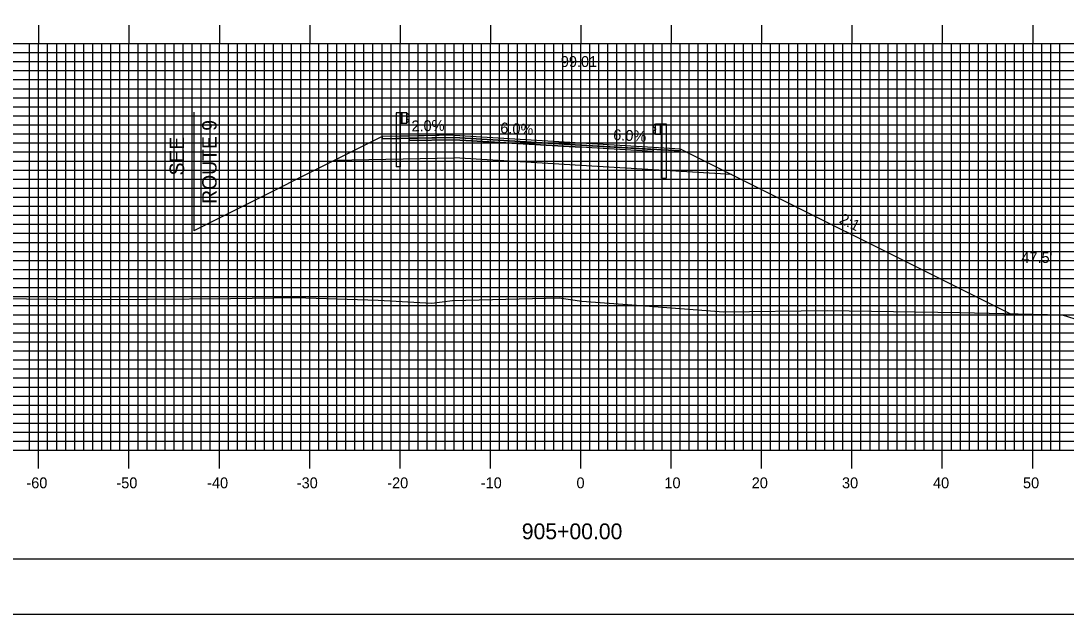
# Model space of a CAD drawing. Extents: x 857504 to 857847, y 364765 to 364985.
# Drawn here: x 857607.4 to 857723, y 364765.2 to 364830.8 of the extents above; entities that cross this region are included whole.
import ezdxf

# ---------------------------------------------------------------- set-up
doc = ezdxf.new("R2010")
doc.units = 0
for name, color, linetype in [('ANNOTATION', 7, 'Continuous'), ('BORDER', 7, 'Continuous'), ('D_Guardrail_Beam_Lt', 7, 'Continuous'), ('D_Guardrail_Beam_Rt', 7, 'Continuous'), ('D_Roadway_Centerline_Text', 7, 'Continuous'), ('D_Roadway_Edge_Shoulder', 7, 'Continuous'), ('D_Roadway_Edge_TW', 7, 'Continuous'), ('D_Roadway_Pavement', 7, 'Continuous'), ('D_Roadway_SlopeLines', 7, 'Continuous'), ('D_Roadway_SubGrade', 7, 'Continuous'), ('D_Text_Standard', 7, 'Continuous'), ('H_V ANNOTATION', 7, 'Continuous'), ('MAJOR', 7, 'Continuous'), ('MINOR', 7, 'Continuous'), ('PLOT BOUNDARY', 7, 'Continuous'), ('S_Roadway_Centerline', 7, 'Continuous')]:
    doc.layers.add(name, color=color, linetype=linetype)

msp = doc.modelspace()

# ---------------------------------------------------------------- linework, layer by layer
at = {"layer": 'BORDER'}
msp.add_lwpolyline([(857519.71, 364771.3), (857839.71, 364771.3), (857839.71, 364981.3), (857519.71, 364981.3)], close=True, dxfattribs=at)
at = {"layer": 'D_Guardrail_Beam_Lt'}
for p, q in [((857648.88, 364820.64), (857648.88, 364814.64)), ((857649.35, 364820.64), (857648.88, 364820.64)), ((857650.04, 364820.64), (857649.35, 364820.64)), ((857649.35, 364820.64), (857649.35, 364819.47)), ((857649.41, 364820.64), (857649.41, 364819.47)), ((857649.52, 364820.64), (857649.52, 364819.47)), ((857650.04, 364819.47), (857650.04, 364820.64)), ((857650.04, 364820.56), (857650.11, 364820.54)), ((857650.04, 364820.09), (857650.04, 364820.02)), ((857650.27, 364820.29), (857650.07, 364820.16)), ((857650.07, 364819.96), (857650.27, 364819.82)), ((857650.13, 364820.54), (857650.27, 364820.44)), ((857650.27, 364819.68), (857650.13, 364819.58)), ((857649.35, 364819.47), (857650.04, 364819.47)), ((857649.37, 364814.64), (857649.37, 364819.47)), ((857650.11, 364819.57), (857650.04, 364819.56)), ((857649.37, 364814.64), (857648.88, 364814.64))]:
    msp.add_line(p, q, dxfattribs=at)
for centre, major_axis, start_param, end_param in [((857650.12, 364820.09), (-0.0789, 0), 5.323254, 6.283185), ((857650.12, 364820.02), (-0.0789, 0), 6.283185, 7.243116), ((857650.1, 364820.5), (0.0417, 0), 0.959931, 1.376053), ((857650.22, 364820.36), (0.0877, 0), 5.323254, 7.243116), ((857650.22, 364819.75), (0.0877, 0), 5.323254, 7.243116), ((857650.1, 364819.61), (0.0417, 0), 4.907132, 5.323254)]:
    msp.add_ellipse(centre, major_axis=major_axis, ratio=0.995501, start_param=start_param, end_param=end_param, dxfattribs=at)
at = {"layer": 'D_Guardrail_Beam_Rt'}
for p, q in [((857677.49, 364819.32), (857677.35, 364819.22)), ((857677.35, 364819.07), (857677.54, 364818.94)), ((857677.54, 364818.74), (857677.35, 364818.6)), ((857677.58, 364819.34), (857677.5, 364819.32)), ((857677.57, 364818.87), (857677.57, 364818.8)), ((857677.58, 364819.42), (857678.27, 364819.42)), ((857677.58, 364818.25), (857677.58, 364819.42)), ((857678.1, 364819.42), (857678.1, 364818.25)), ((857678.2, 364819.42), (857678.2, 364818.25)), ((857678.27, 364819.42), (857678.74, 364819.42)), ((857678.27, 364819.42), (857678.27, 364818.25)), ((857678.74, 364819.42), (857678.74, 364813.42)), ((857677.35, 364818.46), (857677.49, 364818.36)), ((857677.5, 364818.35), (857677.58, 364818.34)), ((857678.27, 364818.25), (857677.58, 364818.25)), ((857678.25, 364813.42), (857678.25, 364818.25)), ((857678.25, 364813.42), (857678.74, 364813.42))]:
    msp.add_line(p, q, dxfattribs=at)
for centre, major_axis, start_param, end_param in [((857677.4, 364819.14), (-0.0877, 0), 5.323254, 7.243116), ((857677.4, 364818.53), (-0.0877, 0), 5.323254, 7.243116), ((857677.51, 364819.28), (-0.0417, 0), 4.907132, 5.323254), ((857677.5, 364818.87), (0.0789, 0), 0, 0.959931), ((857677.5, 364818.8), (0.0789, 0), 5.323254, 6.283185), ((857677.51, 364818.39), (-0.0417, 0), 0.959931, 1.376053)]:
    msp.add_ellipse(centre, major_axis=major_axis, ratio=0.995501, start_param=start_param, end_param=end_param, dxfattribs=at)
at = {"layer": 'D_Roadway_Edge_Shoulder'}
for points in [[(857655.31, 364818.16), (857650.31, 364818.06), (857650.31, 364818.06), (857647.31, 364818), (857647.31, 364817.75), (857650.31, 364817.81), (857655.31, 364817.91)], [(857655.31, 364818.16), (857647.31, 364818), (857647.31, 364817.75), (857655.31, 364817.91)], [(857669.31, 364817.32), (857677.31, 364816.84), (857677.31, 364816.84), (857680.31, 364816.66), (857680.31, 364816.41), (857669.31, 364817.07)]]:
    msp.add_lwpolyline(points, close=True, dxfattribs=at)
at = {"layer": 'D_Roadway_Edge_TW'}
msp.add_lwpolyline([(857655.31, 364818.16), (857669.31, 364817.32), (857669.31, 364817.07), (857655.31, 364817.91)], close=True, dxfattribs=at)
at = {"layer": 'D_Roadway_Pavement'}
for points in [[(857655.31, 364817.91), (857647.31, 364817.75), (857650.31, 364817.81), (857650.31, 364817.56), (857655.31, 364817.66)], [(857655.31, 364817.91), (857650.31, 364817.81), (857650.31, 364817.56), (857655.31, 364817.66)], [(857655.31, 364817.91), (857669.31, 364817.07), (857669.31, 364816.82), (857655.31, 364817.66)]]:
    msp.add_lwpolyline(points, close=True, dxfattribs=at)
for points in [[(857669.31, 364817.07), (857669.31, 364816.82)], [(857669.31, 364817.07), (857669.31, 364816.82)], [(857669.31, 364817.07), (857669.31, 364816.82)], [(857669.31, 364817.07), (857677.31, 364816.59), (857677.31, 364816.34), (857669.31, 364816.82)], [(857669.31, 364817.07), (857669.31, 364816.82)]]:
    msp.add_lwpolyline(points, dxfattribs=at)
at = {"layer": 'D_Roadway_SlopeLines'}
for points in [[(857647.31, 364818), (857626.48, 364807.58)], [(857680.31, 364816.66), (857716.79, 364798.42)]]:
    msp.add_lwpolyline(points, dxfattribs=at)
at = {"layer": 'D_Roadway_SubGrade'}
msp.add_line((857626.48, 364820.72), (857626.48, 364807.58), dxfattribs=at)
for points in [[(857655.31, 364817.66), (857650.31, 364817.56), (857650.31, 364817.81), (857647.31, 364817.75), (857647.31, 364818), (857642.1, 364815.39), (857655.31, 364815.66)], [(857655.31, 364817.66), (857650.31, 364817.56), (857650.31, 364817.81), (857647.31, 364817.75), (857647.31, 364818), (857642.1, 364815.39), (857655.31, 364815.66)], [(857655.31, 364817.66), (857669.31, 364816.82), (857669.31, 364814.82), (857655.31, 364815.66)], [(857669.31, 364816.82), (857669.31, 364817.07), (857680.31, 364816.41), (857680.31, 364816.66), (857685.99, 364813.82), (857669.31, 364814.82)]]:
    msp.add_lwpolyline(points, close=True, dxfattribs=at)
at = {"layer": 'MAJOR'}
for p, q in [((857609.31, 364830.31), (857609.31, 364828.3)), ((857619.31, 364830.31), (857619.31, 364828.3)), ((857629.31, 364830.31), (857629.31, 364828.3)), ((857639.31, 364830.31), (857639.31, 364828.3)), ((857649.31, 364830.31), (857649.31, 364828.3)), ((857659.31, 364830.31), (857659.31, 364828.3)), ((857669.31, 364830.31), (857669.31, 364828.3)), ((857679.31, 364830.31), (857679.31, 364828.3)), ((857689.31, 364830.31), (857689.31, 364828.3)), ((857699.31, 364830.31), (857699.31, 364828.3)), ((857709.31, 364830.31), (857709.31, 364828.3)), ((857719.31, 364830.31), (857719.31, 364828.3)), ((857529.31, 364828.3), (857809.31, 364828.3)), ((857529.31, 364828.3), (857809.31, 364828.3)), ((857609.31, 364783.3), (857609.31, 364828.3)), ((857619.31, 364783.3), (857619.31, 364828.3)), ((857629.31, 364783.3), (857629.31, 364828.3)), ((857639.31, 364783.3), (857639.31, 364828.3)), ((857649.31, 364783.3), (857649.31, 364828.3)), ((857659.31, 364783.3), (857659.31, 364828.3)), ((857669.31, 364783.3), (857669.31, 364828.3)), ((857679.31, 364783.3), (857679.31, 364828.3)), ((857689.31, 364783.3), (857689.31, 364828.3)), ((857699.31, 364783.3), (857699.31, 364828.3)), ((857709.31, 364783.3), (857709.31, 364828.3)), ((857719.31, 364783.3), (857719.31, 364828.3)), ((857529.31, 364823.3), (857809.31, 364823.3)), ((857529.31, 364818.3), (857809.31, 364818.3)), ((857529.31, 364813.3), (857809.31, 364813.3)), ((857529.31, 364808.3), (857809.31, 364808.3)), ((857529.31, 364803.3), (857809.31, 364803.3)), ((857529.31, 364798.3), (857809.31, 364798.3)), ((857529.31, 364793.3), (857809.31, 364793.3)), ((857529.31, 364788.3), (857809.31, 364788.3)), ((857529.31, 364783.3), (857809.31, 364783.3)), ((857529.31, 364783.3), (857809.31, 364783.3)), ((857609.31, 364781.3), (857609.31, 364783.3)), ((857619.31, 364781.3), (857619.31, 364783.3)), ((857629.31, 364781.3), (857629.31, 364783.3)), ((857639.31, 364781.3), (857639.31, 364783.3)), ((857649.31, 364781.3), (857649.31, 364783.3)), ((857659.31, 364781.3), (857659.31, 364783.3)), ((857669.31, 364781.3), (857669.31, 364783.3)), ((857679.31, 364781.3), (857679.31, 364783.3)), ((857689.31, 364781.3), (857689.31, 364783.3)), ((857699.31, 364781.3), (857699.31, 364783.3)), ((857709.31, 364781.3), (857709.31, 364783.3)), ((857719.31, 364781.3), (857719.31, 364783.3))]:
    msp.add_line(p, q, dxfattribs=at)
at = {"layer": 'MINOR'}
for p, q in [((857608.31, 364783.3), (857608.31, 364828.3)), ((857610.31, 364783.3), (857610.31, 364828.3)), ((857611.31, 364783.3), (857611.31, 364828.3)), ((857612.31, 364783.3), (857612.31, 364828.3)), ((857613.31, 364783.3), (857613.31, 364828.3)), ((857614.31, 364783.3), (857614.31, 364828.3)), ((857615.31, 364783.3), (857615.31, 364828.3)), ((857616.31, 364783.3), (857616.31, 364828.3)), ((857617.31, 364783.3), (857617.31, 364828.3)), ((857618.31, 364783.3), (857618.31, 364828.3)), ((857620.31, 364783.3), (857620.31, 364828.3)), ((857621.31, 364783.3), (857621.31, 364828.3)), ((857622.31, 364783.3), (857622.31, 364828.3)), ((857623.31, 364783.3), (857623.31, 364828.3)), ((857624.31, 364783.3), (857624.31, 364828.3)), ((857625.31, 364783.3), (857625.31, 364828.3)), ((857626.31, 364783.3), (857626.31, 364828.3)), ((857627.31, 364783.3), (857627.31, 364828.3)), ((857628.31, 364783.3), (857628.31, 364828.3)), ((857630.31, 364783.3), (857630.31, 364828.3)), ((857631.31, 364783.3), (857631.31, 364828.3)), ((857632.31, 364783.3), (857632.31, 364828.3)), ((857633.31, 364783.3), (857633.31, 364828.3)), ((857634.31, 364783.3), (857634.31, 364828.3)), ((857635.31, 364783.3), (857635.31, 364828.3)), ((857636.31, 364783.3), (857636.31, 364828.3)), ((857637.31, 364783.3), (857637.31, 364828.3)), ((857638.31, 364783.3), (857638.31, 364828.3)), ((857640.31, 364783.3), (857640.31, 364828.3)), ((857641.31, 364783.3), (857641.31, 364828.3)), ((857642.31, 364783.3), (857642.31, 364828.3)), ((857643.31, 364783.3), (857643.31, 364828.3)), ((857644.31, 364783.3), (857644.31, 364828.3)), ((857645.31, 364783.3), (857645.31, 364828.3)), ((857646.31, 364783.3), (857646.31, 364828.3)), ((857647.31, 364783.3), (857647.31, 364828.3)), ((857648.31, 364783.3), (857648.31, 364828.3)), ((857650.31, 364783.3), (857650.31, 364828.3)), ((857651.31, 364783.3), (857651.31, 364828.3)), ((857652.31, 364783.3), (857652.31, 364828.3)), ((857653.31, 364783.3), (857653.31, 364828.3)), ((857654.31, 364783.3), (857654.31, 364828.3)), ((857655.31, 364783.3), (857655.31, 364828.3)), ((857656.31, 364783.3), (857656.31, 364828.3)), ((857657.31, 364783.3), (857657.31, 364828.3)), ((857658.31, 364783.3), (857658.31, 364828.3)), ((857660.31, 364783.3), (857660.31, 364828.3)), ((857661.31, 364783.3), (857661.31, 364828.3)), ((857662.31, 364783.3), (857662.31, 364828.3)), ((857663.31, 364783.3), (857663.31, 364828.3)), ((857664.31, 364783.3), (857664.31, 364828.3)), ((857665.31, 364783.3), (857665.31, 364828.3)), ((857666.31, 364783.3), (857666.31, 364828.3)), ((857667.31, 364783.3), (857667.31, 364828.3)), ((857668.31, 364783.3), (857668.31, 364828.3)), ((857670.31, 364783.3), (857670.31, 364828.3)), ((857671.31, 364783.3), (857671.31, 364828.3)), ((857672.31, 364783.3), (857672.31, 364828.3)), ((857673.31, 364783.3), (857673.31, 364828.3)), ((857674.31, 364783.3), (857674.31, 364828.3)), ((857675.31, 364783.3), (857675.31, 364828.3)), ((857676.31, 364783.3), (857676.31, 364828.3)), ((857677.31, 364783.3), (857677.31, 364828.3)), ((857678.31, 364783.3), (857678.31, 364828.3)), ((857680.31, 364783.3), (857680.31, 364828.3)), ((857681.31, 364783.3), (857681.31, 364828.3)), ((857682.31, 364783.3), (857682.31, 364828.3)), ((857683.31, 364783.3), (857683.31, 364828.3)), ((857684.31, 364783.3), (857684.31, 364828.3)), ((857685.31, 364783.3), (857685.31, 364828.3)), ((857686.31, 364783.3), (857686.31, 364828.3)), ((857687.31, 364783.3), (857687.31, 364828.3)), ((857688.31, 364783.3), (857688.31, 364828.3)), ((857690.31, 364783.3), (857690.31, 364828.3)), ((857691.31, 364783.3), (857691.31, 364828.3)), ((857692.31, 364783.3), (857692.31, 364828.3)), ((857693.31, 364783.3), (857693.31, 364828.3)), ((857694.31, 364783.3), (857694.31, 364828.3)), ((857695.31, 364783.3), (857695.31, 364828.3)), ((857696.31, 364783.3), (857696.31, 364828.3)), ((857697.31, 364783.3), (857697.31, 364828.3)), ((857698.31, 364783.3), (857698.31, 364828.3)), ((857700.31, 364783.3), (857700.31, 364828.3)), ((857701.31, 364783.3), (857701.31, 364828.3)), ((857702.31, 364783.3), (857702.31, 364828.3)), ((857703.31, 364783.3), (857703.31, 364828.3)), ((857704.31, 364783.3), (857704.31, 364828.3)), ((857705.31, 364783.3), (857705.31, 364828.3)), ((857706.31, 364783.3), (857706.31, 364828.3)), ((857707.31, 364783.3), (857707.31, 364828.3)), ((857708.31, 364783.3), (857708.31, 364828.3)), ((857710.31, 364783.3), (857710.31, 364828.3)), ((857711.31, 364783.3), (857711.31, 364828.3)), ((857712.31, 364783.3), (857712.31, 364828.3)), ((857713.31, 364783.3), (857713.31, 364828.3)), ((857714.31, 364783.3), (857714.31, 364828.3)), ((857715.31, 364783.3), (857715.31, 364828.3)), ((857716.31, 364783.3), (857716.31, 364828.3)), ((857717.31, 364783.3), (857717.31, 364828.3)), ((857718.31, 364783.3), (857718.31, 364828.3)), ((857720.31, 364783.3), (857720.31, 364828.3)), ((857721.31, 364783.3), (857721.31, 364828.3)), ((857722.31, 364783.3), (857722.31, 364828.3)), ((857529.31, 364827.3), (857809.31, 364827.3)), ((857529.31, 364826.3), (857809.31, 364826.3)), ((857529.31, 364825.3), (857809.31, 364825.3)), ((857529.31, 364824.3), (857809.31, 364824.3)), ((857529.31, 364822.3), (857809.31, 364822.3)), ((857529.31, 364821.3), (857809.31, 364821.3)), ((857529.31, 364820.3), (857809.31, 364820.3)), ((857529.31, 364819.3), (857809.31, 364819.3)), ((857529.31, 364817.3), (857809.31, 364817.3)), ((857529.31, 364816.3), (857809.31, 364816.3)), ((857529.31, 364815.3), (857809.31, 364815.3)), ((857529.31, 364814.3), (857809.31, 364814.3)), ((857529.31, 364812.3), (857809.31, 364812.3)), ((857529.31, 364811.3), (857809.31, 364811.3)), ((857529.31, 364810.3), (857809.31, 364810.3)), ((857529.31, 364809.3), (857809.31, 364809.3)), ((857529.31, 364807.3), (857809.31, 364807.3)), ((857529.31, 364806.3), (857809.31, 364806.3)), ((857529.31, 364805.3), (857809.31, 364805.3)), ((857529.31, 364804.3), (857809.31, 364804.3)), ((857529.31, 364802.3), (857809.31, 364802.3)), ((857529.31, 364801.3), (857809.31, 364801.3)), ((857529.31, 364800.3), (857809.31, 364800.3)), ((857529.31, 364799.3), (857809.31, 364799.3)), ((857529.31, 364797.3), (857809.31, 364797.3)), ((857529.31, 364796.3), (857809.31, 364796.3)), ((857529.31, 364795.3), (857809.31, 364795.3)), ((857529.31, 364794.3), (857809.31, 364794.3)), ((857529.31, 364792.3), (857809.31, 364792.3)), ((857529.31, 364791.3), (857809.31, 364791.3)), ((857529.31, 364790.3), (857809.31, 364790.3)), ((857529.31, 364789.3), (857809.31, 364789.3)), ((857529.31, 364787.3), (857809.31, 364787.3)), ((857529.31, 364786.3), (857809.31, 364786.3)), ((857529.31, 364785.3), (857809.31, 364785.3)), ((857529.31, 364784.3), (857809.31, 364784.3))]:
    msp.add_line(p, q, dxfattribs=at)
at = {"layer": 'PLOT BOUNDARY'}
msp.add_lwpolyline([(857503.52, 364765.18), (857843.52, 364765.18), (857843.52, 364985.18), (857503.52, 364985.18)], close=True, dxfattribs=at)
at = {"layer": 'S_Roadway_Centerline'}
msp.add_lwpolyline([(857604.88, 364800.09), (857614.12, 364799.97), (857621.43, 364800.01), (857630.55, 364800.08), (857637.75, 364800.22), (857646.89, 364799.92), (857652.82, 364799.59), (857655.1, 364799.87), (857666.92, 364800.16), (857669.42, 364799.8), (857675.47, 364799.34), (857685.08, 364798.62), (857696.56, 364798.76), (857711.26, 364798.53), (857722.59, 364798.3), (857726.78, 364796.97)], dxfattribs=at)

# ---------------------------------------------------------------- texts
at = {"layer": 'ANNOTATION'}
for s, height, rotation, p in [('ROUTE 9', 1.6, 90, (857629.01, 364810.56)), ('2.0%', 1.2, 1.1458, (857650.58, 364818.57)), ('6.0%', 1.2, 356.5055, (857660.37, 364818.38)), ('6.0%', 1.2, 356.6438, (857672.87, 364817.63)), ('SEE', 1.6, 90, (857625.41, 364813.7)), ('2:1', 1.2, 333.4349, (857697.82, 364808.5))]:
    msp.add_text(s, height=height, rotation=rotation, dxfattribs=at).set_placement(p)
at = {"layer": 'D_Roadway_Centerline_Text'}
msp.add_text('99.01', height=1.2, dxfattribs=at).set_placement((857667.1, 364825.7))
at = {"layer": 'D_Text_Standard'}
msp.add_text("47.5'", height=1.2, dxfattribs=at).set_placement((857718.06, 364804.03))
at = {"layer": 'H_V ANNOTATION'}
for s, height, p in [('-60', 1.2, (857607.96, 364779.1)), ('-50', 1.2, (857617.92, 364779.1)), ('-40', 1.2, (857627.96, 364779.1)), ('-30', 1.2, (857637.88, 364779.1)), ('-20', 1.2, (857647.89, 364779.1)), ('-10', 1.2, (857658.24, 364779.1)), ('0', 1.2, (857668.83, 364779.1)), ('10', 1.2, (857678.56, 364779.1)), ('20', 1.2, (857688.22, 364779.1)), ('30', 1.2, (857698.21, 364779.1)), ('40', 1.2, (857708.28, 364779.1)), ('50', 1.2, (857718.24, 364779.1)), ('905+00.00', 1.75, (857662.78, 364773.46))]:
    msp.add_text(s, height=height, dxfattribs=at).set_placement(p)

doc.saveas('drawing.dxf')
